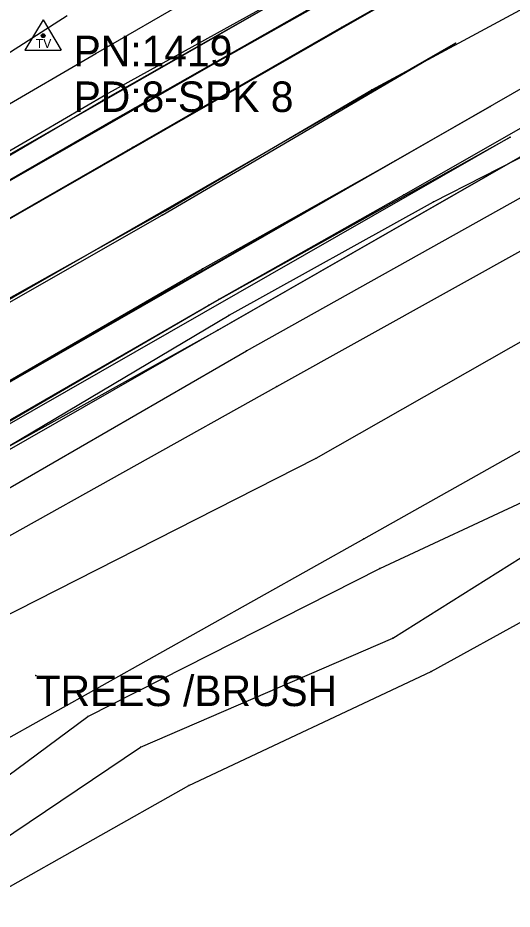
# Model space of a CAD drawing. Extents: x 1419505 to 1434054, y 1956910 to 1968644.
# Drawn here: x 1422173.5 to 1422254.5, y 1958347.6 to 1958493.7 of the extents above; entities that cross this region are included whole.
import ezdxf

# ---------------------------------------------------------------- set-up
doc = ezdxf.new("R2010")
doc.units = 0
for name, color, linetype in [('S_BREAKLINE', 7, 'Continuous'), ('S_DITCHLINE', 7, 'Continuous'), ('S_EDGE_PAVEMENT', 7, 'Continuous'), ('S_GRD_PT_SYM', 7, 'Continuous'), ('S_MSC_PT_SYM', 7, 'Continuous'), ('S_PAVEMENT_CROWN', 7, 'Continuous'), ('S_RDW_PT_SYM', 7, 'Continuous'), ('S_SECONDARY_CTL', 7, 'Continuous'), ('S_SECONDARY_CTL_ANNOT', 7, 'Continuous'), ('S_SHOULDER', 7, 'Continuous'), ('S_SURVEY_TEXT_ANNOT', 7, 'Continuous')]:
    doc.layers.add(name, color=color, linetype=linetype)

msp = doc.modelspace()

# ---------------------------------------------------------------- linework, layer by layer
at = {"layer": 'S_BREAKLINE'}
for p, q in [((1422186.2514, 1958487.8382), (1422241.3359, 1958519.7802)), ((1422234.7195, 1958507.1234), (1421697.9208, 1958199.8056)), ((1422187.4834, 1958480.1927), (1422234.7195, 1958507.1234)), ((1422187.8885, 1958481.1578), (1422222.3557, 1958500.178)), ((1422156.3914, 1958477.9886), (1422181.5471, 1958494.0806)), ((1422160.1887, 1958472.6572), (1422186.2514, 1958487.8382)), ((1422133.2899, 1958449.1747), (1422187.8885, 1958481.1578)), ((1422134.9521, 1958449.3267), (1422187.4834, 1958480.1927)), ((1422241.6089, 1958463.5616), (1422274.197, 1958480.1797)), ((1422210.957, 1958439.103), (1422271.3309, 1958472.8312)), ((1422256.1529, 1958471.0691), (1421717.7711, 1958162.8162)), ((1422206.2847, 1958442.5003), (1422256.1529, 1958471.0691)), ((1422215.9603, 1958433.2477), (1422275.0181, 1958466.1618)), ((1422208.1238, 1958444.9764), (1422241.6089, 1958463.5616)), ((1422222.4167, 1958421.5319), (1422280.3424, 1958454.536)), ((1422152.0082, 1958411.6493), (1422208.1238, 1958444.9764)), ((1422156.7455, 1958415.0575), (1422206.2847, 1958442.5003)), ((1422230.2062, 1958408.28), (1422286.3168, 1958439.9261)), ((1422160.1877, 1958409.7551), (1422210.957, 1958439.103)), ((1422163.0459, 1958403.7638), (1422215.9603, 1958433.2477)), ((1422241.2239, 1958386.5516), (1422318.8209, 1958429.3004)), ((1422170.0513, 1958394.9302), (1422222.4167, 1958421.5319)), ((1422128.0116, 1958351.0774), (1422230.2062, 1958408.28)), ((1422201.5004, 1958367.8264), (1422241.2239, 1958386.5516)), ((1422134.688, 1958330.235), (1422201.5004, 1958367.8264))]:
    msp.add_line(p, q, dxfattribs=at)
at = {"layer": 'S_DITCHLINE'}
for p, q in [((1422232.8314, 1958403.4037), (1422292.6242, 1958431.3445)), ((1422234.9805, 1958392.024), (1422294.1113, 1958429.1984)), ((1422184.9633, 1958379.1352), (1422232.8314, 1958403.4037)), ((1422193.5728, 1958374.1108), (1422234.9805, 1958392.024)), ((1422131.2908, 1958339.4226), (1422184.9633, 1958379.1352)), ((1422133.632, 1958333.8432), (1422193.5728, 1958374.1108))]:
    msp.add_line(p, q, dxfattribs=at)
at = {"layer": 'S_EDGE_PAVEMENT'}
for p, q in [((1422226.608, 1958492.1505), (1422259.5411, 1958510.9647)), ((1422239.4358, 1958499.3739), (1421702.5421, 1958191.435)), ((1422191.4917, 1958471.9822), (1422239.4358, 1958499.3739)), ((1422192.2648, 1958472.4452), (1422226.608, 1958492.1505)), ((1422235.3145, 1958470.24), (1422269.5047, 1958489.9113)), ((1422250.9195, 1958479.1606), (1421712.8678, 1958170.5937)), ((1422202.8354, 1958451.7399), (1422250.9195, 1958479.1606)), ((1422137.9622, 1958441.2382), (1422192.2648, 1958472.4452)), ((1422139.9844, 1958442.4573), (1422191.4917, 1958471.9822)), ((1422203.7465, 1958452.5369), (1422235.3145, 1958470.24)), ((1422148.1119, 1958420.3578), (1422203.7465, 1958452.5369)), ((1422152.2122, 1958422.78), (1422202.8354, 1958451.7399))]:
    msp.add_line(p, q, dxfattribs=at)
at = {"layer": 'S_GRD_PT_SYM'}
for points in [[(1422186.2514, 1958487.8382), (1422186.2514, 1958487.8882), (1422186.2514, 1958487.8382), (1422186.2014, 1958487.8382), (1422186.2514, 1958487.8382), (1422186.2514, 1958487.7882), (1422186.2514, 1958487.8382), (1422186.3014, 1958487.8382)], [(1422187.8885, 1958481.1578), (1422187.8885, 1958481.2078), (1422187.8885, 1958481.1578), (1422187.8385, 1958481.1578), (1422187.8885, 1958481.1578), (1422187.8885, 1958481.1078), (1422187.8885, 1958481.1578), (1422187.9385, 1958481.1578)], [(1422187.4834, 1958480.1927), (1422187.4834, 1958480.2427), (1422187.4834, 1958480.1927), (1422187.4334, 1958480.1927), (1422187.4834, 1958480.1927), (1422187.4834, 1958480.1427), (1422187.4834, 1958480.1927), (1422187.5334, 1958480.1927)], [(1422241.6089, 1958463.5616), (1422241.6089, 1958463.6116), (1422241.6089, 1958463.5616), (1422241.5589, 1958463.5616), (1422241.6089, 1958463.5616), (1422241.6089, 1958463.5116), (1422241.6089, 1958463.5616), (1422241.6589, 1958463.5616)], [(1422208.1238, 1958444.9764), (1422208.1238, 1958445.0264), (1422208.1238, 1958444.9764), (1422208.0738, 1958444.9764), (1422208.1238, 1958444.9764), (1422208.1238, 1958444.9264), (1422208.1238, 1958444.9764), (1422208.1738, 1958444.9764)], [(1422206.2847, 1958442.5003), (1422206.2847, 1958442.5503), (1422206.2847, 1958442.5003), (1422206.2347, 1958442.5003), (1422206.2847, 1958442.5003), (1422206.2847, 1958442.4503), (1422206.2847, 1958442.5003), (1422206.3347, 1958442.5003)], [(1422210.957, 1958439.103), (1422210.957, 1958439.153), (1422210.957, 1958439.103), (1422210.907, 1958439.103), (1422210.957, 1958439.103), (1422210.957, 1958439.053), (1422210.957, 1958439.103), (1422211.007, 1958439.103)], [(1422215.9603, 1958433.2477), (1422215.9603, 1958433.2977), (1422215.9603, 1958433.2477), (1422215.9103, 1958433.2477), (1422215.9603, 1958433.2477), (1422215.9603, 1958433.1977), (1422215.9603, 1958433.2477), (1422216.0103, 1958433.2477)], [(1422222.4167, 1958421.5319), (1422222.4167, 1958421.5819), (1422222.4167, 1958421.5319), (1422222.3667, 1958421.5319), (1422222.4167, 1958421.5319), (1422222.4167, 1958421.4819), (1422222.4167, 1958421.5319), (1422222.4667, 1958421.5319)], [(1422230.2062, 1958408.28), (1422230.2062, 1958408.33), (1422230.2062, 1958408.28), (1422230.1562, 1958408.28), (1422230.2062, 1958408.28), (1422230.2062, 1958408.23), (1422230.2062, 1958408.28), (1422230.2562, 1958408.28)], [(1422232.8314, 1958403.4037), (1422232.8314, 1958403.4537), (1422232.8314, 1958403.4037), (1422232.7814, 1958403.4037), (1422232.8314, 1958403.4037), (1422232.8314, 1958403.3537), (1422232.8314, 1958403.4037), (1422232.8814, 1958403.4037)], [(1422234.9805, 1958392.024), (1422234.9805, 1958392.074), (1422234.9805, 1958392.024), (1422234.9305, 1958392.024), (1422234.9805, 1958392.024), (1422234.9805, 1958391.974), (1422234.9805, 1958392.024), (1422235.0305, 1958392.024)], [(1422241.2239, 1958386.5516), (1422241.2239, 1958386.6016), (1422241.2239, 1958386.5516), (1422241.1739, 1958386.5516), (1422241.2239, 1958386.5516), (1422241.2239, 1958386.5016), (1422241.2239, 1958386.5516), (1422241.2739, 1958386.5516)], [(1422184.9633, 1958379.1352), (1422184.9633, 1958379.1852), (1422184.9633, 1958379.1352), (1422184.9133, 1958379.1352), (1422184.9633, 1958379.1352), (1422184.9633, 1958379.0852), (1422184.9633, 1958379.1352), (1422185.0133, 1958379.1352)], [(1422193.5728, 1958374.1108), (1422193.5728, 1958374.1608), (1422193.5728, 1958374.1108), (1422193.5228, 1958374.1108), (1422193.5728, 1958374.1108), (1422193.5728, 1958374.0608), (1422193.5728, 1958374.1108), (1422193.6228, 1958374.1108)], [(1422201.5004, 1958367.8264), (1422201.5004, 1958367.8764), (1422201.5004, 1958367.8264), (1422201.4504, 1958367.8264), (1422201.5004, 1958367.8264), (1422201.5004, 1958367.7764), (1422201.5004, 1958367.8264), (1422201.5504, 1958367.8264)]]:
    msp.add_lwpolyline(points, dxfattribs=at)
at = {"layer": 'S_MSC_PT_SYM'}
msp.add_lwpolyline([(1422176.4137, 1958385.8666), (1422176.4137, 1958385.9166), (1422176.4137, 1958385.8666), (1422176.3637, 1958385.8666), (1422176.4137, 1958385.8666), (1422176.4137, 1958385.8166), (1422176.4137, 1958385.8666), (1422176.4637, 1958385.8666)], dxfattribs=at)
at = {"layer": 'S_PAVEMENT_CROWN'}
for p, q in [((1422231.5023, 1958481.8808), (1422265.2935, 1958500.111)), ((1422245.2512, 1958489.5463), (1421708.2975, 1958181.3584)), ((1422197.1311, 1958461.3425), (1422245.2512, 1958489.5463)), ((1422197.6671, 1958462.0865), (1422231.5023, 1958481.8808)), ((1422142.8236, 1958431.3225), (1422197.6671, 1958462.0865)), ((1422146.1268, 1958432.2546), (1422197.1311, 1958461.3425))]:
    msp.add_line(p, q, dxfattribs=at)
at = {"layer": 'S_RDW_PT_SYM'}
for points in [[(1422226.608, 1958492.1505), (1422226.608, 1958492.2005), (1422226.608, 1958492.1505), (1422226.558, 1958492.1505), (1422226.608, 1958492.1505), (1422226.608, 1958492.1005), (1422226.608, 1958492.1505), (1422226.658, 1958492.1505)], [(1422245.2512, 1958489.5463), (1422245.2512, 1958489.5963), (1422245.2512, 1958489.5463), (1422245.2012, 1958489.5463), (1422245.2512, 1958489.5463), (1422245.2512, 1958489.4963), (1422245.2512, 1958489.5463), (1422245.3012, 1958489.5463)], [(1422231.5023, 1958481.8808), (1422231.5023, 1958481.9308), (1422231.5023, 1958481.8808), (1422231.4523, 1958481.8808), (1422231.5023, 1958481.8808), (1422231.5023, 1958481.8308), (1422231.5023, 1958481.8808), (1422231.5523, 1958481.8808)], [(1422250.9195, 1958479.1606), (1422250.9195, 1958479.2106), (1422250.9195, 1958479.1606), (1422250.8695, 1958479.1606), (1422250.9195, 1958479.1606), (1422250.9195, 1958479.1106), (1422250.9195, 1958479.1606), (1422250.9695, 1958479.1606)], [(1422189.0865, 1958476.9025), (1422189.0865, 1958476.9525), (1422189.0865, 1958476.9025), (1422189.0365, 1958476.9025), (1422189.0865, 1958476.9025), (1422189.0865, 1958476.8525), (1422189.0865, 1958476.9025), (1422189.1365, 1958476.9025)], [(1422190.1426, 1958477.4545), (1422190.1426, 1958477.5045), (1422190.1426, 1958477.4545), (1422190.0926, 1958477.4545), (1422190.1426, 1958477.4545), (1422190.1426, 1958477.4045), (1422190.1426, 1958477.4545), (1422190.1926, 1958477.4545)], [(1422254.1918, 1958474.1573), (1422254.1918, 1958474.2073), (1422254.1918, 1958474.1573), (1422254.1418, 1958474.1573), (1422254.1918, 1958474.1573), (1422254.1918, 1958474.1073), (1422254.1918, 1958474.1573), (1422254.2418, 1958474.1573)], [(1422191.4917, 1958471.9822), (1422191.4917, 1958472.0322), (1422191.4917, 1958471.9822), (1422191.4417, 1958471.9822), (1422191.4917, 1958471.9822), (1422191.4917, 1958471.9322), (1422191.4917, 1958471.9822), (1422191.5417, 1958471.9822)], [(1422192.2648, 1958472.4452), (1422192.2648, 1958472.4952), (1422192.2648, 1958472.4452), (1422192.2148, 1958472.4452), (1422192.2648, 1958472.4452), (1422192.2648, 1958472.3952), (1422192.2648, 1958472.4452), (1422192.3148, 1958472.4452)], [(1422235.3145, 1958470.24), (1422235.3145, 1958470.29), (1422235.3145, 1958470.24), (1422235.2645, 1958470.24), (1422235.3145, 1958470.24), (1422235.3145, 1958470.19), (1422235.3145, 1958470.24), (1422235.3645, 1958470.24)], [(1422236.7396, 1958464.6817), (1422236.7396, 1958464.7317), (1422236.7396, 1958464.6817), (1422236.6896, 1958464.6817), (1422236.7396, 1958464.6817), (1422236.7396, 1958464.6317), (1422236.7396, 1958464.6817), (1422236.7896, 1958464.6817)], [(1422197.6671, 1958462.0865), (1422197.6671, 1958462.1365), (1422197.6671, 1958462.0865), (1422197.6171, 1958462.0865), (1422197.6671, 1958462.0865), (1422197.6671, 1958462.0365), (1422197.6671, 1958462.0865), (1422197.7171, 1958462.0865)], [(1422197.1311, 1958461.3425), (1422197.1311, 1958461.3925), (1422197.1311, 1958461.3425), (1422197.0811, 1958461.3425), (1422197.1311, 1958461.3425), (1422197.1311, 1958461.2925), (1422197.1311, 1958461.3425), (1422197.1811, 1958461.3425)], [(1422202.8354, 1958451.7399), (1422202.8354, 1958451.7899), (1422202.8354, 1958451.7399), (1422202.7854, 1958451.7399), (1422202.8354, 1958451.7399), (1422202.8354, 1958451.6899), (1422202.8354, 1958451.7399), (1422202.8854, 1958451.7399)], [(1422203.7465, 1958452.5369), (1422203.7465, 1958452.5869), (1422203.7465, 1958452.5369), (1422203.6965, 1958452.5369), (1422203.7465, 1958452.5369), (1422203.7465, 1958452.4869), (1422203.7465, 1958452.5369), (1422203.7965, 1958452.5369)], [(1422206.5097, 1958447.5796), (1422206.5097, 1958447.6296), (1422206.5097, 1958447.5796), (1422206.4597, 1958447.5796), (1422206.5097, 1958447.5796), (1422206.5097, 1958447.5296), (1422206.5097, 1958447.5796), (1422206.5597, 1958447.5796)], [(1422204.8096, 1958446.6245), (1422204.8096, 1958446.6745), (1422204.8096, 1958446.6245), (1422204.7596, 1958446.6245), (1422204.8096, 1958446.6245), (1422204.8096, 1958446.5745), (1422204.8096, 1958446.6245), (1422204.8596, 1958446.6245)]]:
    msp.add_lwpolyline(points, dxfattribs=at)
at = {"layer": 'S_SECONDARY_CTL'}
for p, q in [((1422177.6228, 1958493.3795), (1422174.6128, 1958488.4256)), ((1422177.6228, 1958493.3795), (1422180.5701, 1958488.4256)), ((1422174.6128, 1958488.4256), (1422180.5701, 1958488.4256))]:
    msp.add_line(p, q, dxfattribs=at)
for radius in [0.3111, 0.1827, 0.1033]:
    msp.add_circle((1422177.6228, 1958490.7694), radius, dxfattribs=at)
at = {"layer": 'S_SHOULDER'}
for p, q in [((1422236.8876, 1958504.0772), (1421699.4589, 1958196.0923)), ((1422189.0865, 1958476.9025), (1422236.8876, 1958504.0772)), ((1422190.1426, 1958477.4545), (1422224.1628, 1958496.6308)), ((1422236.7396, 1958464.6817), (1422272.5179, 1958485.08)), ((1422134.806, 1958445.4775), (1422190.1426, 1958477.4545)), ((1422136.9252, 1958446.9125), (1422189.0865, 1958476.9025)), ((1422254.1918, 1958474.1573), (1421715.306, 1958165.4004)), ((1422204.8096, 1958446.6245), (1422254.1918, 1958474.1573)), ((1422206.5097, 1958447.5796), (1422236.7396, 1958464.6817)), ((1422150.4291, 1958415.2545), (1422206.5097, 1958447.5796)), ((1422155.0904, 1958417.7157), (1422204.8096, 1958446.6245))]:
    msp.add_line(p, q, dxfattribs=at)

# ---------------------------------------------------------------- texts
at = {"layer": 'S_SECONDARY_CTL'}
msp.add_text('TV', height=1.5, rotation=360, dxfattribs=at).set_placement((1422176.4181, 1958488.7581))
at = {"layer": 'S_SECONDARY_CTL_ANNOT'}
for s, p in [('PN:1419', (1422182.6228, 1958485.7694)), ('PD:8-SPK 8', (1422182.6228, 1958478.2694))]:
    msp.add_text(s, height=5, dxfattribs=at).set_placement(p)
at = {"layer": 'S_SURVEY_TEXT_ANNOT'}
msp.add_text('TREES /BRUSH', height=5, dxfattribs=at).set_placement((1422176.4137, 1958380.8666))

doc.saveas('drawing.dxf')
